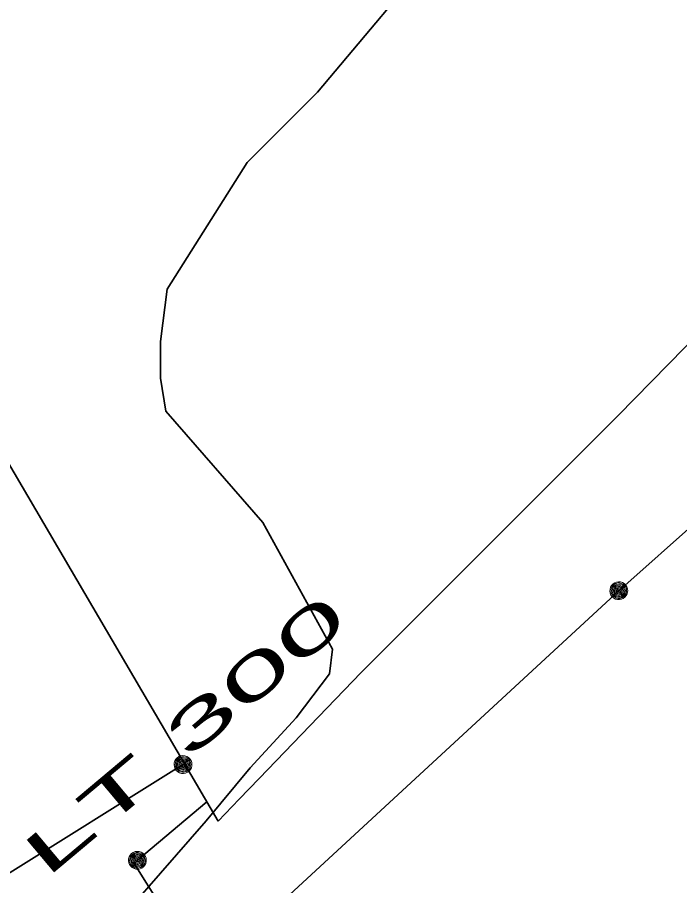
# Model space of a CAD drawing. Extents: x -867104 to -866746, y -1014489 to -1014255.
# Drawn here: x -866882.88 to -866865.74, y -1014464.82 to -1014442.34 of the extents above; entities that cross this region are included whole.
import ezdxf

# ---------------------------------------------------------------- set-up
doc = ezdxf.new("R2010")
doc.units = 0
doc.header["$LTSCALE"] = 0.44
for name, color, linetype, lineweight in [('1', 7, 'Continuous', 35), ('12', 7, 'Continuous', 13), ('21', 7, 'Continuous', 35), ('32', 7, 'Continuous', 13)]:
    doc.layers.add(name, color=color, linetype=linetype, lineweight=lineweight)

msp = doc.modelspace()

# ---------------------------------------------------------------- linework, layer by layer
at = {"layer": '1'}
msp.add_line((-866878.55, -1014461.654), (-866901.68, -1014476.123), dxfattribs=at)
for points in [[(-866877.679, -1014463.149), (-866884.593, -1014451.356), (-866912.586, -1014412.658), (-867006.516, -1014398.571), (-867098.057, -1014351.101)], [(-866840.01, -1014396.11), (-866844.69, -1014400.78), (-866847.06, -1014402.96), (-866848.88, -1014406.15), (-866860.28, -1014424.67), (-866871.77, -1014440.29), (-866875.11, -1014444.27), (-866876.93, -1014446.09), (-866879, -1014449.37), (-866879.17, -1014450.73), (-866879.17, -1014451.68), (-866879.03, -1014452.53), (-866876.52, -1014455.41), (-866874.72, -1014458.69), (-866874.8, -1014459.33), (-866875.66, -1014460.47), (-866876.85, -1014461.77), (-866877.992, -1014463.135), (-866881.12, -1014466.73), (-866885.53, -1014471.37), (-866892.467, -1014476.423)], [(-866829.29, -1014413.39), (-866837.14, -1014421.79), (-866844.09, -1014428.8), (-866855.26, -1014440.32), (-866867.329, -1014452.641), (-866873.974, -1014459.295), (-866875.079, -1014460.444), (-866876.617, -1014462.044), (-866877.133, -1014462.581), (-866877.679, -1014463.149)], [(-866877.97, -1014462.642), (-866879.77, -1014464.16), (-866879.853, -1014464.243)], [(-866872.103, -1014480.579), (-866873.16, -1014479.02), (-866874.64, -1014476.65), (-866874.86, -1014476.38), (-866874.94, -1014476.16), (-866875.02, -1014476.02), (-866875.1, -1014475.88), (-866873.85, -1014475.16), (-866874, -1014474.83), (-866877.08, -1014468.77), (-866877.461, -1014468.135), (-866878.488, -1014466.421), (-866879.853, -1014464.243)]]:
    msp.add_lwpolyline(points, dxfattribs=at)
at = {"layer": '12'}
for points in [[(-866878.358, -1014461.68), (-866878.365, -1014461.628), (-866878.382, -1014461.578), (-866878.411, -1014461.534), (-866878.448, -1014461.497), (-866878.493, -1014461.47), (-866878.543, -1014461.453), (-866878.596, -1014461.449), (-866878.647, -1014461.456), (-866878.696, -1014461.475), (-866878.74, -1014461.504), (-866878.776, -1014461.543), (-866878.802, -1014461.588), (-866878.818, -1014461.639), (-866878.821, -1014461.691), (-866878.813, -1014461.743), (-866878.793, -1014461.792), (-866878.762, -1014461.835), (-866878.723, -1014461.869), (-866878.677, -1014461.895), (-866878.625, -1014461.909), (-866878.573, -1014461.911), (-866878.522, -1014461.901), (-866878.473, -1014461.88), (-866878.431, -1014461.849), (-866878.397, -1014461.808), (-866878.373, -1014461.762), (-866878.36, -1014461.711)], [(-866878.389, -1014461.68), (-866878.395, -1014461.631), (-866878.412, -1014461.585), (-866878.44, -1014461.545), (-866878.477, -1014461.513), (-866878.521, -1014461.491), (-866878.569, -1014461.48), (-866878.618, -1014461.48), (-866878.664, -1014461.493), (-866878.708, -1014461.517), (-866878.744, -1014461.55), (-866878.771, -1014461.591), (-866878.787, -1014461.638), (-866878.791, -1014461.687), (-866878.784, -1014461.735), (-866878.765, -1014461.78), (-866878.735, -1014461.82), (-866878.696, -1014461.851), (-866878.652, -1014461.871), (-866878.605, -1014461.881), (-866878.556, -1014461.879), (-866878.509, -1014461.864), (-866878.466, -1014461.839), (-866878.431, -1014461.805), (-866878.406, -1014461.763), (-866878.392, -1014461.716)], [(-866878.419, -1014461.68), (-866878.424, -1014461.635), (-866878.441, -1014461.593), (-866878.47, -1014461.558), (-866878.505, -1014461.531), (-866878.548, -1014461.514), (-866878.593, -1014461.509), (-866878.637, -1014461.515), (-866878.679, -1014461.534), (-866878.713, -1014461.562), (-866878.74, -1014461.599), (-866878.757, -1014461.641), (-866878.761, -1014461.686), (-866878.754, -1014461.731), (-866878.735, -1014461.772), (-866878.706, -1014461.806), (-866878.669, -1014461.832), (-866878.625, -1014461.848), (-866878.581, -1014461.851), (-866878.536, -1014461.843), (-866878.495, -1014461.823), (-866878.462, -1014461.794), (-866878.436, -1014461.756), (-866878.422, -1014461.713)], [(-866878.449, -1014461.68), (-866878.453, -1014461.639), (-866878.472, -1014461.602), (-866878.499, -1014461.571), (-866878.534, -1014461.55), (-866878.574, -1014461.539), (-866878.615, -1014461.541), (-866878.654, -1014461.554), (-866878.688, -1014461.578), (-866878.713, -1014461.61), (-866878.728, -1014461.648), (-866878.73, -1014461.689), (-866878.723, -1014461.729), (-866878.703, -1014461.765), (-866878.674, -1014461.794), (-866878.637, -1014461.813), (-866878.597, -1014461.821), (-866878.556, -1014461.817), (-866878.517, -1014461.802), (-866878.485, -1014461.776), (-866878.463, -1014461.742), (-866878.45, -1014461.703)], [(-866878.478, -1014461.68), (-866878.483, -1014461.644), (-866878.502, -1014461.612), (-866878.527, -1014461.587), (-866878.561, -1014461.572), (-866878.598, -1014461.569), (-866878.632, -1014461.577), (-866878.664, -1014461.597), (-866878.686, -1014461.625), (-866878.7, -1014461.659), (-866878.7, -1014461.696), (-866878.689, -1014461.731), (-866878.668, -1014461.76), (-866878.637, -1014461.781), (-866878.603, -1014461.791), (-866878.566, -1014461.789), (-866878.532, -1014461.775), (-866878.505, -1014461.752), (-866878.485, -1014461.72), (-866878.478, -1014461.685)], [(-866878.509, -1014461.68), (-866878.514, -1014461.649), (-866878.531, -1014461.623), (-866878.556, -1014461.606), (-866878.587, -1014461.599), (-866878.618, -1014461.603), (-866878.645, -1014461.62), (-866878.663, -1014461.644), (-866878.671, -1014461.675), (-866878.667, -1014461.705), (-866878.652, -1014461.733), (-866878.627, -1014461.752), (-866878.598, -1014461.761), (-866878.566, -1014461.758), (-866878.539, -1014461.744), (-866878.519, -1014461.72), (-866878.509, -1014461.691)], [(-866878.539, -1014461.68), (-866878.544, -1014461.656), (-866878.561, -1014461.638), (-866878.583, -1014461.629), (-866878.608, -1014461.632), (-866878.629, -1014461.646), (-866878.64, -1014461.668), (-866878.64, -1014461.693), (-866878.627, -1014461.714), (-866878.608, -1014461.728), (-866878.583, -1014461.731), (-866878.559, -1014461.722), (-866878.544, -1014461.704)], [(-866878.569, -1014461.68), (-866878.574, -1014461.665), (-866878.588, -1014461.659), (-866878.603, -1014461.663), (-866878.61, -1014461.677), (-866878.607, -1014461.692), (-866878.593, -1014461.701), (-866878.578, -1014461.698), (-866878.569, -1014461.686)], [(-866879.539, -1014464.16), (-866879.545, -1014464.108), (-866879.562, -1014464.058), (-866879.591, -1014464.014), (-866879.628, -1014463.977), (-866879.673, -1014463.95), (-866879.723, -1014463.933), (-866879.776, -1014463.929), (-866879.828, -1014463.936), (-866879.877, -1014463.955), (-866879.92, -1014463.984), (-866879.956, -1014464.023), (-866879.982, -1014464.068), (-866879.998, -1014464.119), (-866880.001, -1014464.171), (-866879.993, -1014464.223), (-866879.973, -1014464.272), (-866879.942, -1014464.315), (-866879.903, -1014464.349), (-866879.857, -1014464.375), (-866879.806, -1014464.389), (-866879.753, -1014464.391), (-866879.702, -1014464.381), (-866879.654, -1014464.36), (-866879.611, -1014464.329), (-866879.577, -1014464.288), (-866879.553, -1014464.242), (-866879.541, -1014464.191)], [(-866879.569, -1014464.16), (-866879.575, -1014464.111), (-866879.592, -1014464.065), (-866879.62, -1014464.025), (-866879.657, -1014463.993), (-866879.701, -1014463.971), (-866879.749, -1014463.96), (-866879.798, -1014463.96), (-866879.845, -1014463.973), (-866879.888, -1014463.997), (-866879.924, -1014464.03), (-866879.951, -1014464.071), (-866879.967, -1014464.118), (-866879.971, -1014464.167), (-866879.964, -1014464.215), (-866879.945, -1014464.26), (-866879.915, -1014464.3), (-866879.877, -1014464.331), (-866879.833, -1014464.351), (-866879.785, -1014464.361), (-866879.736, -1014464.359), (-866879.689, -1014464.344), (-866879.646, -1014464.319), (-866879.612, -1014464.285), (-866879.586, -1014464.243), (-866879.572, -1014464.196)], [(-866879.599, -1014464.16), (-866879.605, -1014464.115), (-866879.622, -1014464.073), (-866879.65, -1014464.038), (-866879.686, -1014464.011), (-866879.728, -1014463.994), (-866879.773, -1014463.989), (-866879.818, -1014463.995), (-866879.859, -1014464.014), (-866879.894, -1014464.042), (-866879.921, -1014464.079), (-866879.937, -1014464.121), (-866879.941, -1014464.166), (-866879.934, -1014464.211), (-866879.915, -1014464.252), (-866879.886, -1014464.286), (-866879.849, -1014464.312), (-866879.806, -1014464.328), (-866879.761, -1014464.331), (-866879.716, -1014464.323), (-866879.676, -1014464.303), (-866879.642, -1014464.274), (-866879.616, -1014464.236), (-866879.602, -1014464.193)], [(-866879.629, -1014464.16), (-866879.634, -1014464.119), (-866879.652, -1014464.082), (-866879.679, -1014464.051), (-866879.714, -1014464.03), (-866879.754, -1014464.019), (-866879.795, -1014464.021), (-866879.834, -1014464.034), (-866879.868, -1014464.058), (-866879.893, -1014464.09), (-866879.908, -1014464.128), (-866879.911, -1014464.169), (-866879.903, -1014464.209), (-866879.883, -1014464.245), (-866879.854, -1014464.274), (-866879.817, -1014464.293), (-866879.777, -1014464.301), (-866879.736, -1014464.297), (-866879.698, -1014464.282), (-866879.666, -1014464.256), (-866879.643, -1014464.222), (-866879.63, -1014464.183)], [(-866879.659, -1014464.16), (-866879.664, -1014464.124), (-866879.682, -1014464.092), (-866879.708, -1014464.067), (-866879.742, -1014464.052), (-866879.778, -1014464.049), (-866879.813, -1014464.057), (-866879.844, -1014464.077), (-866879.867, -1014464.105), (-866879.88, -1014464.139), (-866879.88, -1014464.176), (-866879.869, -1014464.211), (-866879.848, -1014464.24), (-866879.818, -1014464.261), (-866879.783, -1014464.271), (-866879.746, -1014464.269), (-866879.712, -1014464.255), (-866879.685, -1014464.232), (-866879.666, -1014464.2), (-866879.659, -1014464.165)], [(-866879.689, -1014464.16), (-866879.694, -1014464.129), (-866879.711, -1014464.103), (-866879.737, -1014464.086), (-866879.767, -1014464.079), (-866879.798, -1014464.083), (-866879.825, -1014464.1), (-866879.843, -1014464.124), (-866879.851, -1014464.155), (-866879.847, -1014464.185), (-866879.832, -1014464.213), (-866879.808, -1014464.232), (-866879.778, -1014464.241), (-866879.747, -1014464.238), (-866879.719, -1014464.224), (-866879.699, -1014464.2), (-866879.689, -1014464.171)], [(-866879.719, -1014464.16), (-866879.724, -1014464.136), (-866879.741, -1014464.118), (-866879.764, -1014464.109), (-866879.788, -1014464.112), (-866879.809, -1014464.126), (-866879.82, -1014464.148), (-866879.82, -1014464.173), (-866879.808, -1014464.194), (-866879.788, -1014464.208), (-866879.763, -1014464.211), (-866879.74, -1014464.202), (-866879.724, -1014464.184)], [(-866879.749, -1014464.16), (-866879.754, -1014464.145), (-866879.769, -1014464.139), (-866879.784, -1014464.143), (-866879.791, -1014464.157), (-866879.787, -1014464.172), (-866879.774, -1014464.181), (-866879.759, -1014464.178), (-866879.749, -1014464.166)]]:
    msp.add_lwpolyline(points, close=True, dxfattribs=at)
at = {"layer": '21'}
for p, q in [((-866867.31, -1014457.18), (-866851.61, -1014443.23)), ((-866882.407, -1014471.12), (-866867.31, -1014457.18))]:
    msp.add_line(p, q, dxfattribs=at)
at = {"layer": '32'}
for points in [[(-866867.079, -1014457.18), (-866867.085, -1014457.128), (-866867.102, -1014457.078), (-866867.131, -1014457.034), (-866867.168, -1014456.997), (-866867.213, -1014456.97), (-866867.263, -1014456.953), (-866867.316, -1014456.949), (-866867.368, -1014456.956), (-866867.417, -1014456.975), (-866867.46, -1014457.004), (-866867.496, -1014457.043), (-866867.522, -1014457.088), (-866867.538, -1014457.139), (-866867.541, -1014457.191), (-866867.533, -1014457.243), (-866867.513, -1014457.292), (-866867.482, -1014457.335), (-866867.443, -1014457.369), (-866867.397, -1014457.395), (-866867.346, -1014457.409), (-866867.293, -1014457.411), (-866867.242, -1014457.401), (-866867.194, -1014457.38), (-866867.151, -1014457.349), (-866867.117, -1014457.308), (-866867.093, -1014457.262), (-866867.081, -1014457.211)], [(-866867.109, -1014457.18), (-866867.115, -1014457.131), (-866867.132, -1014457.085), (-866867.16, -1014457.045), (-866867.197, -1014457.013), (-866867.241, -1014456.991), (-866867.289, -1014456.98), (-866867.338, -1014456.98), (-866867.385, -1014456.993), (-866867.428, -1014457.017), (-866867.464, -1014457.05), (-866867.491, -1014457.091), (-866867.507, -1014457.138), (-866867.511, -1014457.187), (-866867.504, -1014457.235), (-866867.485, -1014457.28), (-866867.455, -1014457.32), (-866867.417, -1014457.351), (-866867.373, -1014457.371), (-866867.325, -1014457.381), (-866867.276, -1014457.379), (-866867.229, -1014457.364), (-866867.186, -1014457.339), (-866867.152, -1014457.305), (-866867.126, -1014457.263), (-866867.112, -1014457.216)], [(-866867.139, -1014457.18), (-866867.145, -1014457.135), (-866867.162, -1014457.093), (-866867.19, -1014457.058), (-866867.226, -1014457.031), (-866867.268, -1014457.014), (-866867.313, -1014457.009), (-866867.358, -1014457.015), (-866867.399, -1014457.034), (-866867.434, -1014457.062), (-866867.461, -1014457.099), (-866867.477, -1014457.141), (-866867.481, -1014457.186), (-866867.474, -1014457.231), (-866867.455, -1014457.272), (-866867.426, -1014457.306), (-866867.389, -1014457.332), (-866867.346, -1014457.348), (-866867.301, -1014457.351), (-866867.256, -1014457.343), (-866867.216, -1014457.323), (-866867.182, -1014457.294), (-866867.156, -1014457.256), (-866867.142, -1014457.213)], [(-866867.169, -1014457.18), (-866867.174, -1014457.139), (-866867.192, -1014457.102), (-866867.219, -1014457.071), (-866867.254, -1014457.05), (-866867.294, -1014457.039), (-866867.335, -1014457.041), (-866867.374, -1014457.054), (-866867.408, -1014457.078), (-866867.433, -1014457.11), (-866867.448, -1014457.148), (-866867.451, -1014457.189), (-866867.443, -1014457.229), (-866867.423, -1014457.265), (-866867.394, -1014457.294), (-866867.357, -1014457.313), (-866867.317, -1014457.321), (-866867.276, -1014457.317), (-866867.238, -1014457.302), (-866867.206, -1014457.276), (-866867.183, -1014457.242), (-866867.17, -1014457.203)], [(-866867.199, -1014457.18), (-866867.204, -1014457.144), (-866867.222, -1014457.112), (-866867.248, -1014457.087), (-866867.282, -1014457.072), (-866867.318, -1014457.069), (-866867.353, -1014457.077), (-866867.384, -1014457.097), (-866867.407, -1014457.125), (-866867.42, -1014457.159), (-866867.42, -1014457.196), (-866867.409, -1014457.231), (-866867.388, -1014457.26), (-866867.358, -1014457.281), (-866867.323, -1014457.291), (-866867.286, -1014457.289), (-866867.252, -1014457.275), (-866867.225, -1014457.252), (-866867.206, -1014457.22), (-866867.199, -1014457.185)], [(-866867.229, -1014457.18), (-866867.234, -1014457.149), (-866867.251, -1014457.123), (-866867.277, -1014457.106), (-866867.307, -1014457.099), (-866867.338, -1014457.103), (-866867.365, -1014457.12), (-866867.383, -1014457.144), (-866867.391, -1014457.175), (-866867.387, -1014457.205), (-866867.372, -1014457.233), (-866867.348, -1014457.252), (-866867.318, -1014457.261), (-866867.287, -1014457.258), (-866867.259, -1014457.244), (-866867.239, -1014457.22), (-866867.229, -1014457.191)], [(-866867.259, -1014457.18), (-866867.264, -1014457.156), (-866867.281, -1014457.138), (-866867.304, -1014457.129), (-866867.328, -1014457.132), (-866867.349, -1014457.146), (-866867.36, -1014457.168), (-866867.36, -1014457.193), (-866867.348, -1014457.214), (-866867.328, -1014457.228), (-866867.303, -1014457.231), (-866867.28, -1014457.222), (-866867.264, -1014457.204)], [(-866867.289, -1014457.18), (-866867.294, -1014457.165), (-866867.309, -1014457.159), (-866867.324, -1014457.163), (-866867.331, -1014457.177), (-866867.327, -1014457.192), (-866867.314, -1014457.201), (-866867.299, -1014457.198), (-866867.289, -1014457.186)]]:
    msp.add_lwpolyline(points, close=True, dxfattribs=at)

# ---------------------------------------------------------------- texts
at = {"layer": '1', "width": 2.25}
msp.add_text('LT 300', height=1.1, rotation=40, dxfattribs=at).set_placement((-866882.134, -1014464.648))

doc.saveas('drawing.dxf')
